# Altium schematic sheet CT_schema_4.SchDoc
size 396 x 205 mm
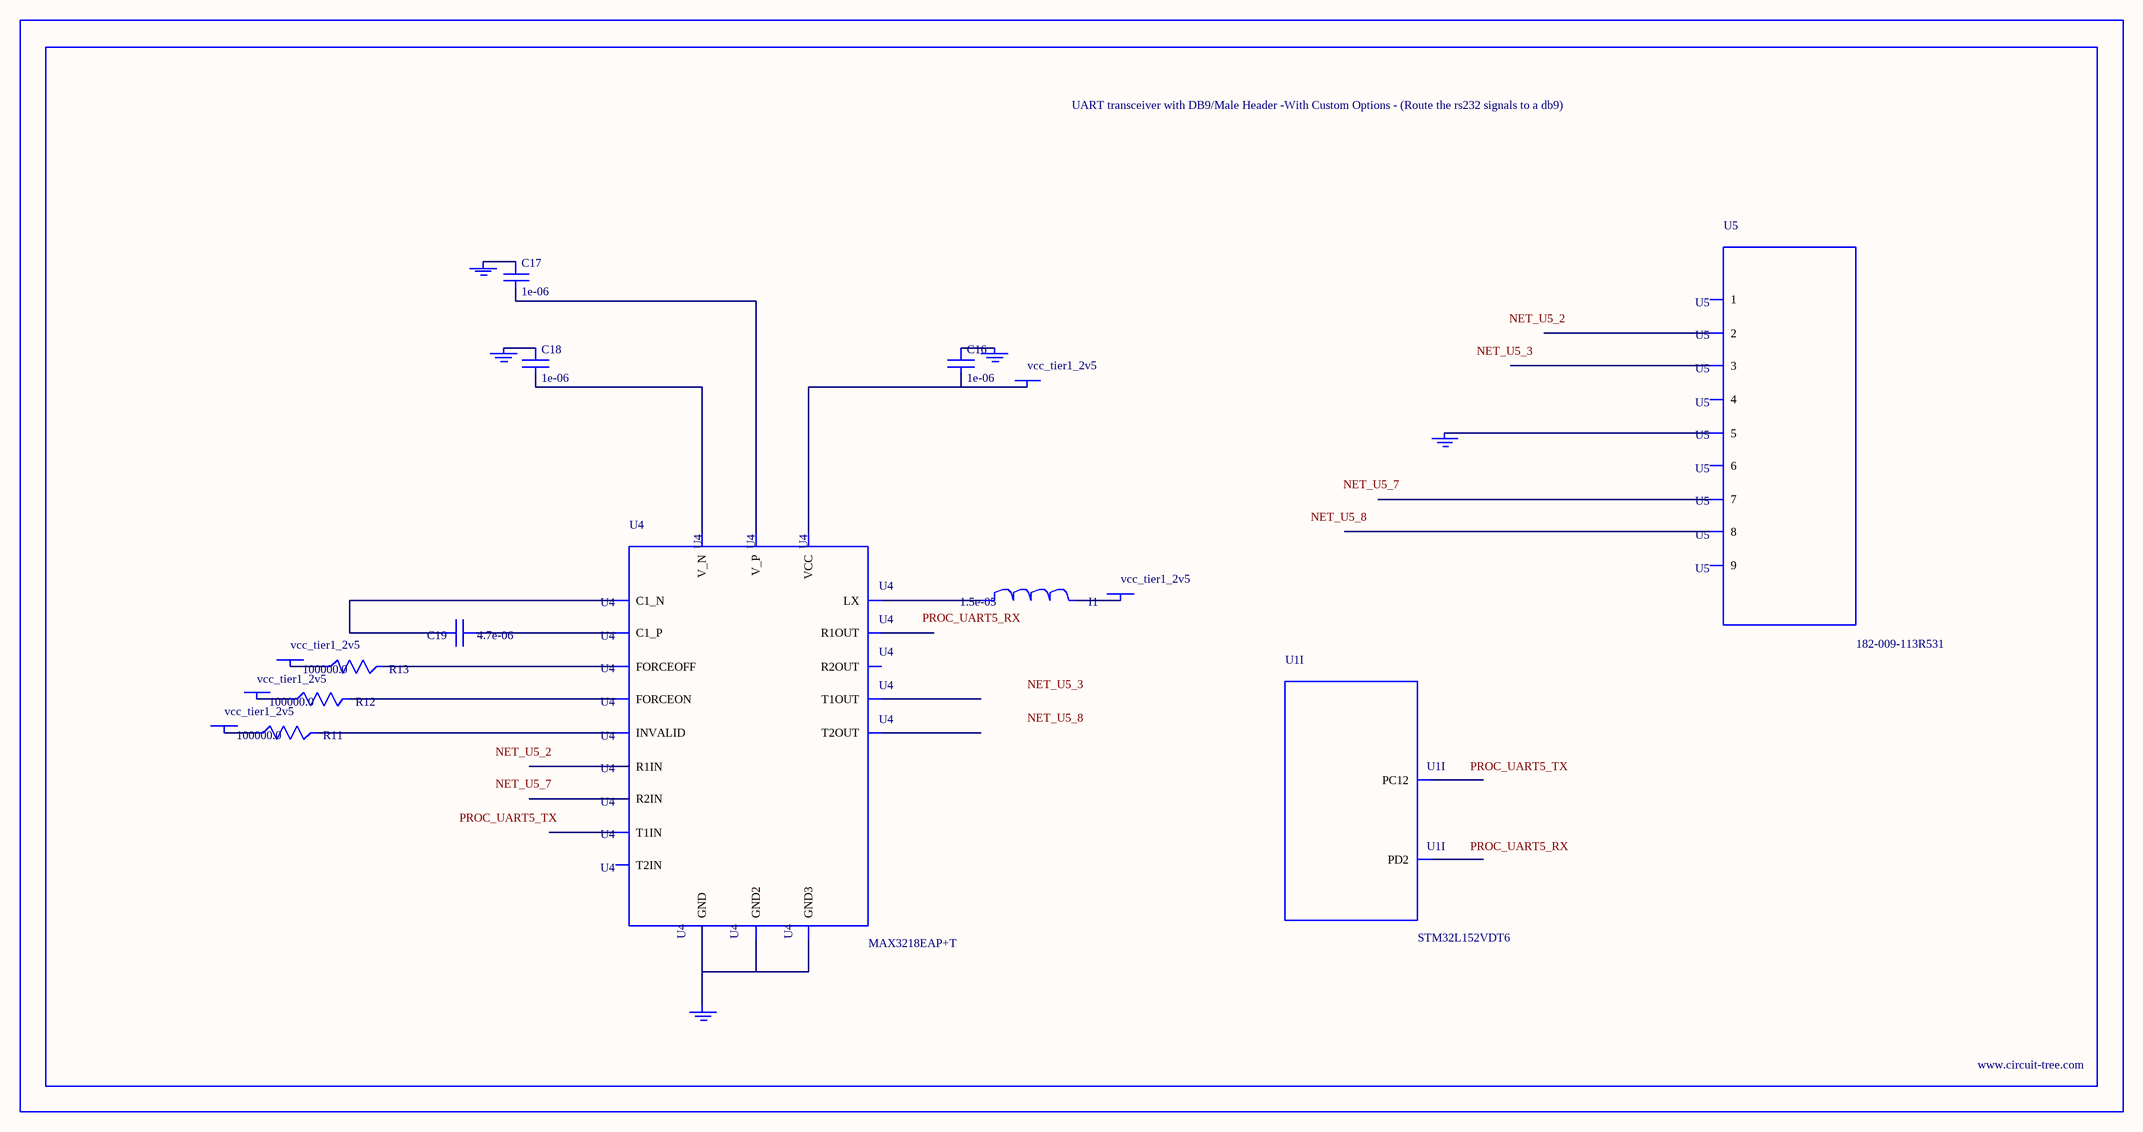
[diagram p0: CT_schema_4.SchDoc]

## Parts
BORDER3  (no value)
C16  1e-06  [C0603]
C17  1e-06  [C0603]
C18  1e-06  [C0603]
C19  4.7e-06  [C0805]
GND_INSTANCE_3_0  (no value)
GND_INSTANCE_3_1  (no value)
GND_INSTANCE_3_2  (no value)
GND_INSTANCE_3_3  (no value)
GND_INSTANCE_3_4  (no value)
I1  1.5e-05  [L1210]
POWER_INSTANCE_3_0  vcc_tier1_2v5
POWER_INSTANCE_3_1  vcc_tier1_2v5
POWER_INSTANCE_3_2  vcc_tier1_2v5
POWER_INSTANCE_3_3  vcc_tier1_2v5
POWER_INSTANCE_3_4  vcc_tier1_2v5
R11  100000.0  [R0603]
R12  100000.0  [R0603]
R13  100000.0  [R0603]
U1  STM32L152VDT6  [LQFP100]  (part I of 10)
U4  MAX3218EAP+T  [SSOP-20]
U5  182-009-113R531  [182-009-MALE]

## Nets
NetC16_1: C16.1 GND_INSTANCE_3_0.0(GND)
NetC16_2: C16.2 POWER_INSTANCE_3_4.0(PWR) U4.6(VCC)
NetC17_1: C17.1 GND_INSTANCE_3_2.0(GND)
NetC17_2: C17.2 U4.19(V_P)
NetC18_1: C18.1 GND_INSTANCE_3_1.0(GND)
NetC18_2: C18.2 U4.15(V_N)
NetC19_1: C19.1 U4.18(C1_P)
NetC19_2: C19.2 U4.16(C1_N)
NetGND_INSTANCE_3_3_0: GND_INSTANCE_3_3.0(GND) U4.5(GND) U4.17(GND2) U4.20(GND3)
NetGND_INSTANCE_3_4_0: GND_INSTANCE_3_4.0(GND) U5.5
NetI1_1: I1.1 U4.1(LX)
NetI1_2: I1.2 POWER_INSTANCE_3_0.0(PWR)
NetPOWER_INSTANCE_3_1_0: POWER_INSTANCE_3_1.0(PWR) R11.1
NetPOWER_INSTANCE_3_2_0: POWER_INSTANCE_3_2.0(PWR) R12.1
NetPOWER_INSTANCE_3_3_0: POWER_INSTANCE_3_3.0(PWR) R13.1
NetR11_2: R11.2 U4.2(INVALID)
NetR12_2: R12.2 U4.3(FORCEON)
NetR13_2: R13.2 U4.4(FORCEOFF)

Not connected (* = marked no-connect by the designer): U1 80(PC12) 83(PD2); U4 7(T1IN) 8(T2IN) 9(R1OUT) 10(R2OUT) 11(R2IN) 12(R1IN) 13(T2OUT) 14(T1OUT); U5 1 2 3 4 6 7 8 9

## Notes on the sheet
- Labels drawn without touching a wire or pin: NET_U5_2, NET_U5_3, NET_U5_7, NET_U5_8, PROC_UART5_RX, PROC_UART5_TX

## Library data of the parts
BORDER3 = BORDER_PAGE3
C16-C18 = C0603C105K3RACTU
C19 = C0805C475K4RACTU
GND_INSTANCE_3_0-GND_INSTANCE_3_4 = GND
I1 = L1210R150MDWIT
POWER_INSTANCE_3_0-POWER_INSTANCE_3_4 = PWR
R11-R13 = RC0603JR-07100KL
